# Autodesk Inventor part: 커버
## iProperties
Company: 한국ATC센터
Created: 2015-05
Part Number: 커버
Document SubType Name: 모델링
Designer: KYOUNG IL JANG
Vendor: CBT Solutions
Author: KYOUNG IL JANG
Comments: 파생
